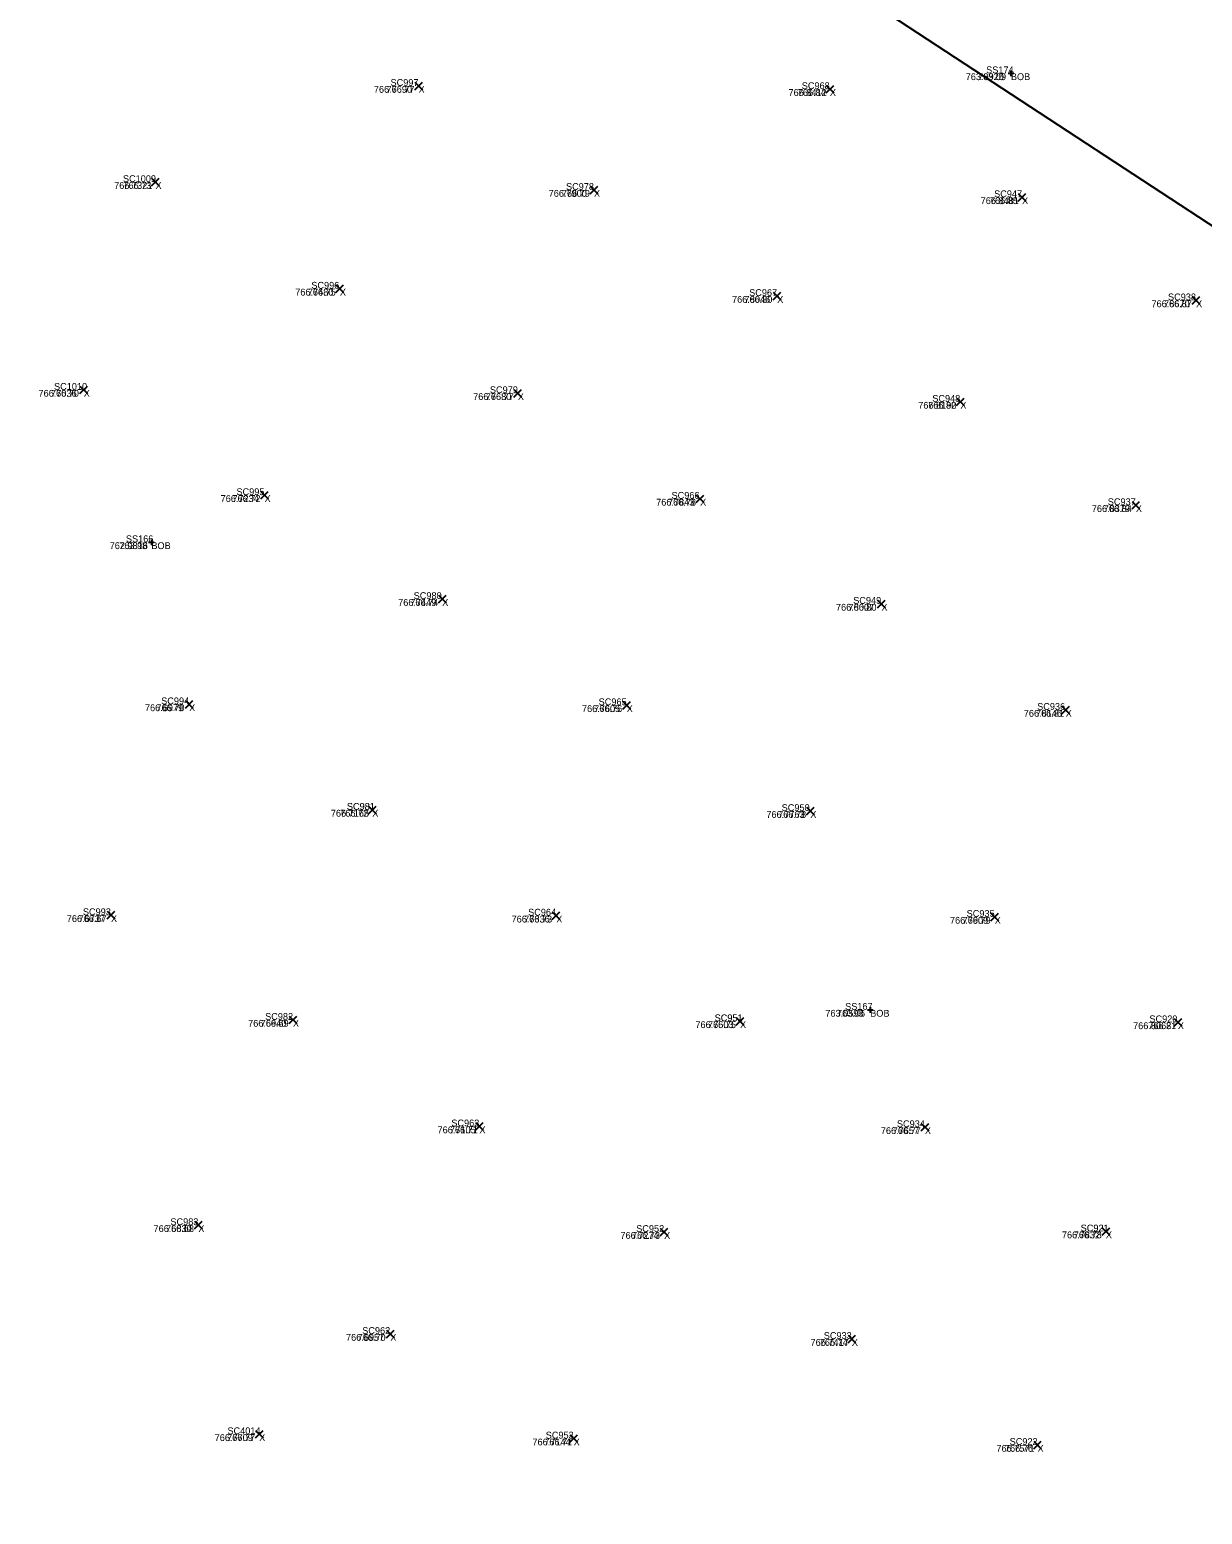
# Model space of a CAD drawing. Extents: x 1845019 to 1877956, y 680444 to 701081.
# Drawn here: x 1857580.97 to 1857591.25, y 694316.04 to 694329.06 of the extents above; entities that cross this region are included whole.
import ezdxf

# ---------------------------------------------------------------- set-up
doc = ezdxf.new("R2010")
doc.units = 0
for name, color, linetype in [('BR_X_SV_Bottom_of_Beam_Text', 7, 'Continuous'), ('SV_X_CL_Survey_20', 7, 'Continuous'), ('SV_X_Random_Point', 7, 'Continuous'), ('SV_X_Text_Comment', 7, 'Continuous'), ('SV_X_Text_Elevation', 7, 'Continuous'), ('SV_X_Text_Name', 7, 'Continuous')]:
    doc.layers.add(name, color=color, linetype=linetype)

msp = doc.modelspace()

# ---------------------------------------------------------------- linework, layer by layer
at = {"layer": 'BR_X_SV_Bottom_of_Beam_Text'}
for p, q in [((1857589.546, 694328.68), (1857589.596, 694328.68)), ((1857589.546, 694328.68), (1857589.596, 694328.68)), ((1857589.571, 694328.705), (1857589.571, 694328.655)), ((1857589.571, 694328.705), (1857589.571, 694328.655)), ((1857589.571, 694328.68), (1857589.571, 694328.68)), ((1857589.571, 694328.68), (1857589.571, 694328.68)), ((1857582.013, 694324.568), (1857582.063, 694324.568)), ((1857582.013, 694324.568), (1857582.063, 694324.568)), ((1857582.038, 694324.593), (1857582.038, 694324.543)), ((1857582.038, 694324.593), (1857582.038, 694324.543)), ((1857582.038, 694324.568), (1857582.038, 694324.568)), ((1857582.038, 694324.568), (1857582.038, 694324.568)), ((1857588.313, 694320.468), (1857588.363, 694320.468)), ((1857588.313, 694320.468), (1857588.363, 694320.468)), ((1857588.338, 694320.493), (1857588.338, 694320.443)), ((1857588.338, 694320.493), (1857588.338, 694320.443)), ((1857588.338, 694320.468), (1857588.338, 694320.468)), ((1857588.338, 694320.468), (1857588.338, 694320.468))]:
    msp.add_line(p, q, dxfattribs=at)
at = {"layer": 'SV_X_CL_Survey_20'}
msp.add_line((1856038.267, 695346.314), (1858797.327, 693536.085), dxfattribs=at)
at = {"layer": 'SV_X_Random_Point'}
for p, q in [((1857584.347, 694328.535), (1857584.413, 694328.602)), ((1857584.347, 694328.602), (1857584.413, 694328.535)), ((1857584.347, 694328.535), (1857584.413, 694328.602)), ((1857584.347, 694328.602), (1857584.413, 694328.535)), ((1857587.951, 694328.508), (1857588.018, 694328.574)), ((1857587.951, 694328.574), (1857588.018, 694328.508)), ((1857587.951, 694328.508), (1857588.018, 694328.574)), ((1857587.951, 694328.574), (1857588.018, 694328.508)), ((1857582.04, 694327.692), (1857582.107, 694327.759)), ((1857582.04, 694327.759), (1857582.107, 694327.692)), ((1857582.04, 694327.692), (1857582.107, 694327.759)), ((1857582.04, 694327.759), (1857582.107, 694327.692)), ((1857585.884, 694327.623), (1857585.951, 694327.69)), ((1857585.884, 694327.69), (1857585.951, 694327.623)), ((1857585.884, 694327.623), (1857585.951, 694327.69)), ((1857585.884, 694327.69), (1857585.951, 694327.623)), ((1857589.636, 694327.56), (1857589.703, 694327.626)), ((1857589.636, 694327.626), (1857589.703, 694327.56)), ((1857589.636, 694327.56), (1857589.703, 694327.626)), ((1857589.636, 694327.626), (1857589.703, 694327.56)), ((1857583.656, 694326.757), (1857583.723, 694326.824)), ((1857583.656, 694326.824), (1857583.723, 694326.757)), ((1857583.656, 694326.757), (1857583.723, 694326.824)), ((1857583.656, 694326.824), (1857583.723, 694326.757)), ((1857587.489, 694326.694), (1857587.556, 694326.76)), ((1857587.489, 694326.76), (1857587.556, 694326.694)), ((1857587.489, 694326.694), (1857587.556, 694326.76)), ((1857587.489, 694326.76), (1857587.556, 694326.694)), ((1857591.161, 694326.656), (1857591.228, 694326.723)), ((1857591.161, 694326.723), (1857591.228, 694326.656)), ((1857591.161, 694326.656), (1857591.228, 694326.723)), ((1857591.161, 694326.723), (1857591.228, 694326.656)), ((1857581.411, 694325.871), (1857581.478, 694325.938)), ((1857581.411, 694325.938), (1857581.478, 694325.871)), ((1857581.411, 694325.871), (1857581.478, 694325.938)), ((1857581.411, 694325.938), (1857581.478, 694325.871)), ((1857585.216, 694325.841), (1857585.283, 694325.908)), ((1857585.216, 694325.908), (1857585.283, 694325.841)), ((1857585.216, 694325.841), (1857585.283, 694325.908)), ((1857585.216, 694325.908), (1857585.283, 694325.841)), ((1857589.095, 694325.766), (1857589.161, 694325.832)), ((1857589.095, 694325.832), (1857589.161, 694325.766)), ((1857589.095, 694325.766), (1857589.161, 694325.832)), ((1857589.095, 694325.832), (1857589.161, 694325.766)), ((1857582.997, 694324.948), (1857583.063, 694325.014)), ((1857582.997, 694325.014), (1857583.063, 694324.948)), ((1857582.997, 694324.948), (1857583.063, 694325.014)), ((1857582.997, 694325.014), (1857583.063, 694324.948)), ((1857586.814, 694324.916), (1857586.88, 694324.982)), ((1857586.814, 694324.982), (1857586.88, 694324.916)), ((1857586.814, 694324.916), (1857586.88, 694324.982)), ((1857586.814, 694324.982), (1857586.88, 694324.916)), ((1857590.633, 694324.86), (1857590.699, 694324.926)), ((1857590.633, 694324.926), (1857590.699, 694324.86)), ((1857590.633, 694324.86), (1857590.699, 694324.926)), ((1857590.633, 694324.926), (1857590.699, 694324.86)), ((1857584.554, 694324.036), (1857584.621, 694324.103)), ((1857584.554, 694324.103), (1857584.621, 694324.036)), ((1857584.554, 694324.036), (1857584.621, 694324.103)), ((1857584.554, 694324.103), (1857584.621, 694324.036)), ((1857588.402, 694323.994), (1857588.469, 694324.061)), ((1857588.402, 694324.061), (1857588.469, 694323.994)), ((1857588.402, 694323.994), (1857588.469, 694324.061)), ((1857588.402, 694324.061), (1857588.469, 694323.994)), ((1857582.336, 694323.114), (1857582.403, 694323.181)), ((1857582.336, 694323.181), (1857582.403, 694323.114)), ((1857582.336, 694323.114), (1857582.403, 694323.181)), ((1857582.336, 694323.181), (1857582.403, 694323.114)), ((1857586.17, 694323.105), (1857586.237, 694323.172)), ((1857586.17, 694323.172), (1857586.237, 694323.105)), ((1857586.17, 694323.105), (1857586.237, 694323.172)), ((1857586.17, 694323.172), (1857586.237, 694323.105)), ((1857590.017, 694323.065), (1857590.084, 694323.132)), ((1857590.017, 694323.132), (1857590.084, 694323.065)), ((1857590.017, 694323.065), (1857590.084, 694323.132)), ((1857590.017, 694323.132), (1857590.084, 694323.065)), ((1857583.94, 694322.188), (1857584.007, 694322.255)), ((1857583.94, 694322.255), (1857584.007, 694322.188)), ((1857583.94, 694322.188), (1857584.007, 694322.255)), ((1857583.94, 694322.255), (1857584.007, 694322.188)), ((1857587.779, 694322.178), (1857587.846, 694322.245)), ((1857587.779, 694322.245), (1857587.846, 694322.178)), ((1857587.779, 694322.178), (1857587.846, 694322.245)), ((1857587.779, 694322.245), (1857587.846, 694322.178)), ((1857581.651, 694321.265), (1857581.717, 694321.332)), ((1857581.651, 694321.332), (1857581.717, 694321.265)), ((1857581.651, 694321.265), (1857581.717, 694321.332)), ((1857581.651, 694321.332), (1857581.717, 694321.265)), ((1857585.552, 694321.261), (1857585.619, 694321.327)), ((1857585.552, 694321.327), (1857585.619, 694321.261)), ((1857585.552, 694321.261), (1857585.619, 694321.327)), ((1857585.552, 694321.327), (1857585.619, 694321.261)), ((1857589.396, 694321.249), (1857589.462, 694321.316)), ((1857589.396, 694321.316), (1857589.462, 694321.249)), ((1857589.396, 694321.249), (1857589.462, 694321.316)), ((1857589.396, 694321.316), (1857589.462, 694321.249)), ((1857583.246, 694320.347), (1857583.313, 694320.413)), ((1857583.246, 694320.413), (1857583.313, 694320.347)), ((1857583.246, 694320.347), (1857583.313, 694320.413)), ((1857583.246, 694320.413), (1857583.313, 694320.347)), ((1857587.163, 694320.335), (1857587.23, 694320.401)), ((1857587.163, 694320.401), (1857587.23, 694320.335)), ((1857587.163, 694320.335), (1857587.23, 694320.401)), ((1857587.163, 694320.401), (1857587.23, 694320.335)), ((1857591.001, 694320.326), (1857591.068, 694320.392)), ((1857591.001, 694320.392), (1857591.068, 694320.326)), ((1857591.001, 694320.326), (1857591.068, 694320.392)), ((1857591.001, 694320.392), (1857591.068, 694320.326)), ((1857584.879, 694319.413), (1857584.946, 694319.48)), ((1857584.879, 694319.48), (1857584.946, 694319.413)), ((1857584.879, 694319.413), (1857584.946, 694319.48)), ((1857584.879, 694319.48), (1857584.946, 694319.413)), ((1857588.784, 694319.406), (1857588.851, 694319.472)), ((1857588.784, 694319.472), (1857588.851, 694319.406)), ((1857588.784, 694319.406), (1857588.851, 694319.472)), ((1857588.784, 694319.472), (1857588.851, 694319.406)), ((1857582.416, 694318.547), (1857582.483, 694318.614)), ((1857582.416, 694318.614), (1857582.483, 694318.547)), ((1857582.416, 694318.547), (1857582.483, 694318.614)), ((1857582.416, 694318.614), (1857582.483, 694318.547)), ((1857586.498, 694318.486), (1857586.565, 694318.553)), ((1857586.498, 694318.553), (1857586.565, 694318.486)), ((1857586.498, 694318.486), (1857586.565, 694318.553)), ((1857586.498, 694318.553), (1857586.565, 694318.486)), ((1857590.37, 694318.492), (1857590.437, 694318.558)), ((1857590.37, 694318.558), (1857590.437, 694318.492)), ((1857590.37, 694318.492), (1857590.437, 694318.558)), ((1857590.37, 694318.558), (1857590.437, 694318.492)), ((1857584.099, 694317.593), (1857584.165, 694317.66)), ((1857584.099, 694317.66), (1857584.165, 694317.593)), ((1857584.099, 694317.593), (1857584.165, 694317.66)), ((1857584.099, 694317.66), (1857584.165, 694317.593)), ((1857588.144, 694317.548), (1857588.21, 694317.615)), ((1857588.144, 694317.615), (1857588.21, 694317.548)), ((1857588.144, 694317.548), (1857588.21, 694317.615)), ((1857588.144, 694317.615), (1857588.21, 694317.548)), ((1857582.95, 694316.714), (1857583.017, 694316.78)), ((1857582.95, 694316.78), (1857583.017, 694316.714)), ((1857582.95, 694316.714), (1857583.017, 694316.78)), ((1857582.95, 694316.78), (1857583.017, 694316.714)), ((1857585.706, 694316.676), (1857585.772, 694316.743)), ((1857585.706, 694316.743), (1857585.772, 694316.676)), ((1857585.706, 694316.676), (1857585.772, 694316.743)), ((1857585.706, 694316.743), (1857585.772, 694316.676)), ((1857589.771, 694316.619), (1857589.837, 694316.686)), ((1857589.771, 694316.686), (1857589.837, 694316.619)), ((1857589.771, 694316.619), (1857589.837, 694316.686)), ((1857589.771, 694316.686), (1857589.837, 694316.619))]:
    msp.add_line(p, q, dxfattribs=at)

# ---------------------------------------------------------------- texts
at = {"layer": 'BR_X_SV_Bottom_of_Beam_Text'}
for s, p in [('763.0920', (1857589.175, 694328.62)), ('763.09', (1857589.283, 694328.62)), ('SS174', (1857589.354, 694328.68)), ('SS174', (1857589.354, 694328.68)), ('BOB', (1857589.571, 694328.62)), ('SS166', (1857581.815, 694324.568)), ('SS166', (1857581.815, 694324.568)), ('762.9816', (1857581.673, 694324.508)), ('762.98', (1857581.757, 694324.508)), ('BOB', (1857582.038, 694324.508)), ('763.0593', (1857587.945, 694320.408)), ('763.06', (1857588.047, 694320.408)), ('SS167', (1857588.118, 694320.468)), ('SS167', (1857588.118, 694320.468)), ('BOB', (1857588.338, 694320.408))]:
    msp.add_text(s, height=0.06, dxfattribs=at).set_placement(p)
at = {"layer": 'SV_X_Text_Comment'}
for p in [(1857584.38, 694328.509), (1857587.984, 694328.481), (1857582.074, 694327.666), (1857585.917, 694327.597), (1857589.669, 694327.533), (1857583.69, 694326.731), (1857587.523, 694326.667), (1857591.194, 694326.629), (1857581.445, 694325.844), (1857585.25, 694325.815), (1857589.128, 694325.739), (1857583.03, 694324.921), (1857586.847, 694324.889), (1857590.666, 694324.833), (1857584.587, 694324.01), (1857588.436, 694323.968), (1857582.369, 694323.087), (1857586.204, 694323.079), (1857590.051, 694323.038), (1857583.974, 694322.162), (1857587.813, 694322.151), (1857581.684, 694321.238), (1857585.586, 694321.234), (1857589.429, 694321.223), (1857583.279, 694320.32), (1857587.197, 694320.308), (1857591.034, 694320.299), (1857584.913, 694319.386), (1857588.817, 694319.379), (1857582.45, 694318.52), (1857586.532, 694318.46), (1857590.403, 694318.465), (1857584.132, 694317.566), (1857588.177, 694317.522), (1857582.983, 694316.687), (1857585.739, 694316.649), (1857589.804, 694316.593)]:
    msp.add_text('X', height=0.06, dxfattribs=at).set_placement(p)
at = {"layer": 'SV_X_Text_Elevation'}
for s, p in [('766.7690', (1857583.988, 694328.509)), ('766.77', (1857584.099, 694328.509)), ('766.8412', (1857587.622, 694328.481)), ('766.84', (1857587.703, 694328.481)), ('766.7321', (1857581.712, 694327.666)), ('766.73', (1857581.793, 694327.666)), ('766.7900', (1857585.52, 694327.597)), ('766.79', (1857585.636, 694327.597)), ('766.8481', (1857589.306, 694327.533)), ('766.85', (1857589.387, 694327.533)), ('766.7480', (1857583.299, 694326.731)), ('766.75', (1857583.409, 694326.731)), ('766.8046', (1857587.127, 694326.667)), ('766.80', (1857587.235, 694326.667)), ('766.8670', (1857590.803, 694326.629)), ('766.87', (1857590.912, 694326.629)), ('766.7036', (1857581.049, 694325.844)), ('766.70', (1857581.158, 694325.844)), ('766.7680', (1857584.858, 694325.815)), ('766.77', (1857584.969, 694325.815)), ('766.8190', (1857588.759, 694325.739)), ('766.82', (1857588.846, 694325.739)), ('766.7234', (1857582.645, 694324.921)), ('766.72', (1857582.749, 694324.921)), ('766.7843', (1857586.462, 694324.889)), ('766.78', (1857586.566, 694324.889)), ('766.8379', (1857590.28, 694324.833)), ('766.84', (1857590.385, 694324.833)), ('766.7449', (1857584.201, 694324.01)), ('766.74', (1857584.307, 694324.01)), ('766.8007', (1857588.038, 694323.968)), ('766.80', (1857588.148, 694323.968)), ('766.6979', (1857581.982, 694323.087)), ('766.70', (1857582.083, 694323.087)), ('766.7605', (1857585.812, 694323.079)), ('766.76', (1857585.919, 694323.079)), ('766.8146', (1857589.684, 694323.038)), ('766.81', (1857589.791, 694323.038)), ('766.7165', (1857583.611, 694322.162)), ('766.72', (1857583.693, 694322.162)), ('766.7763', (1857587.428, 694322.151)), ('766.78', (1857587.531, 694322.151)), ('766.6737', (1857581.297, 694321.238)), ('766.67', (1857581.401, 694321.238)), ('766.7336', (1857585.195, 694321.234)), ('766.73', (1857585.305, 694321.234)), ('766.7909', (1857589.037, 694321.223)), ('766.79', (1857589.148, 694321.223)), ('766.6940', (1857582.886, 694320.32)), ('766.69', (1857582.996, 694320.32)), ('766.7503', (1857586.806, 694320.308)), ('766.75', (1857586.916, 694320.308)), ('766.8062', (1857590.642, 694320.299)), ('766.81', (1857590.775, 694320.299)), ('766.7105', (1857584.546, 694319.386)), ('766.71', (1857584.654, 694319.386)), ('766.7657', (1857588.431, 694319.379)), ('766.77', (1857588.536, 694319.379)), ('766.6830', (1857582.057, 694318.52)), ('766.68', (1857582.166, 694318.52)), ('766.7274', (1857586.149, 694318.46)), ('766.73', (1857586.25, 694318.46)), ('766.7832', (1857590.018, 694318.465)), ('766.78', (1857590.122, 694318.465)), ('766.6957', (1857583.744, 694317.566)), ('766.70', (1857583.846, 694317.566)), ('766.7417', (1857587.815, 694317.522)), ('766.74', (1857587.896, 694317.522)), ('766.7709', (1857582.593, 694316.687)), ('766.77', (1857582.702, 694316.687)), ('766.7144', (1857585.378, 694316.649)), ('766.71', (1857585.481, 694316.649)), ('766.7571', (1857589.444, 694316.593)), ('766.76', (1857589.519, 694316.593))]:
    msp.add_text(s, height=0.06, dxfattribs=at).set_placement(p)
at = {"layer": 'SV_X_Text_Name'}
for s, p in [('SC997', (1857584.134, 694328.569)), ('SC997', (1857584.134, 694328.569)), ('SC968', (1857587.738, 694328.541)), ('SC968', (1857587.738, 694328.541)), ('SC1009', (1857581.789, 694327.726)), ('SC1009', (1857581.789, 694327.726)), ('SC978', (1857585.672, 694327.657)), ('SC978', (1857585.672, 694327.657)), ('SC947', (1857589.424, 694327.593)), ('SC947', (1857589.424, 694327.593)), ('SC996', (1857583.44, 694326.791)), ('SC996', (1857583.44, 694326.791)), ('SC967', (1857587.277, 694326.727)), ('SC967', (1857587.277, 694326.727)), ('SC938', (1857590.948, 694326.689)), ('SC938', (1857590.948, 694326.689)), ('SC1010', (1857581.185, 694325.904)), ('SC1010', (1857581.185, 694325.904)), ('SC979', (1857585.005, 694325.875)), ('SC979', (1857585.005, 694325.875)), ('SC948', (1857588.882, 694325.799)), ('SC948', (1857588.882, 694325.799)), ('SC995', (1857582.784, 694324.981)), ('SC995', (1857582.784, 694324.981)), ('SC966', (1857586.597, 694324.949)), ('SC966', (1857586.597, 694324.949)), ('SC937', (1857590.42, 694324.893)), ('SC937', (1857590.42, 694324.893)), ('SC980', (1857584.337, 694324.07)), ('SC980', (1857584.337, 694324.07)), ('SC949', (1857588.189, 694324.028)), ('SC949', (1857588.189, 694324.028)), ('SC994', (1857582.124, 694323.147)), ('SC994', (1857582.124, 694323.147)), ('SC965', (1857585.958, 694323.139)), ('SC965', (1857585.958, 694323.139)), ('SC936', (1857589.801, 694323.098)), ('SC936', (1857589.801, 694323.098)), ('SC981', (1857583.752, 694322.222)), ('SC981', (1857583.751, 694322.222)), ('SC950', (1857587.562, 694322.211)), ('SC950', (1857587.562, 694322.211)), ('SC993', (1857581.438, 694321.298)), ('SC993', (1857581.438, 694321.298)), ('SC964', (1857585.34, 694321.294)), ('SC964', (1857585.34, 694321.294)), ('SC935', (1857589.183, 694321.283)), ('SC935', (1857589.183, 694321.283)), ('SC982', (1857583.035, 694320.38)), ('SC982', (1857583.035, 694320.38)), ('SC951', (1857586.974, 694320.368)), ('SC951', (1857586.975, 694320.368)), ('SC920', (1857590.785, 694320.359)), ('SC920', (1857590.785, 694320.359)), ('SC963', (1857584.667, 694319.446)), ('SC963', (1857584.667, 694319.446)), ('SC934', (1857588.572, 694319.439)), ('SC934', (1857588.572, 694319.439)), ('SC983', (1857582.205, 694318.58)), ('SC983', (1857582.205, 694318.58)), ('SC952', (1857586.287, 694318.52)), ('SC952', (1857586.287, 694318.52)), ('SC921', (1857590.182, 694318.525)), ('SC921', (1857590.183, 694318.525)), ('SC962', (1857583.886, 694317.626)), ('SC962', (1857583.886, 694317.626)), ('SC933', (1857587.931, 694317.582)), ('SC933', (1857587.931, 694317.582)), ('SC4014', (1857582.705, 694316.747)), ('SC4014', (1857582.705, 694316.747)), ('SC953', (1857585.494, 694316.709)), ('SC953', (1857585.494, 694316.709)), ('SC922', (1857589.56, 694316.653)), ('SC922', (1857589.56, 694316.653))]:
    msp.add_text(s, height=0.06, dxfattribs=at).set_placement(p)

doc.saveas('drawing.dxf')
